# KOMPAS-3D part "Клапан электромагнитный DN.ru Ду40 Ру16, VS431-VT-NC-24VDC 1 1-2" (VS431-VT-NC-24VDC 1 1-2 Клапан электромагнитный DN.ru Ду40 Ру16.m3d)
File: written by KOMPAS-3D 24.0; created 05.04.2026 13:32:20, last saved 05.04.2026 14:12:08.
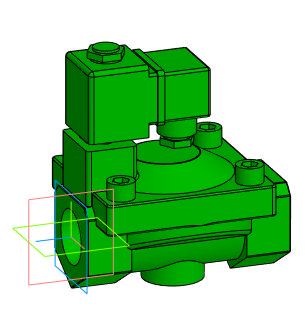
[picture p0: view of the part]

Document properties: Автор: artio; Полное имя файла: C:\Users\artio\OneDrive\Рабочий стол\Клапан электромагнитный DN.ru\VS431\VS431-VT-NC\VS431-VT-NC-24VDC\Ду40\VS431-VT-NC-24VDC 1 1-2 Клапан электромагнитный DN.ru Ду40 Ру16.m3d

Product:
- Body: Тело 1  | qty 1
    Масса: 3.859459
- Part/product: Клапан электромагнитный DN.ru Ду40 Ру16  | designation VS431-VT-NC-24VDC 1 1-2
    Масса: 2.285
    Раздел спецификации: Прочие изделия
    Примечание: D130-04758
    additional columns: ef56311e-7521-43dc-8291-0e6108b3d81d; artio; c; Шероховатость не задана; Да

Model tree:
1. Операция без истории:1

Expressions: VS431-VT-NC-24VDC 1 1-2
